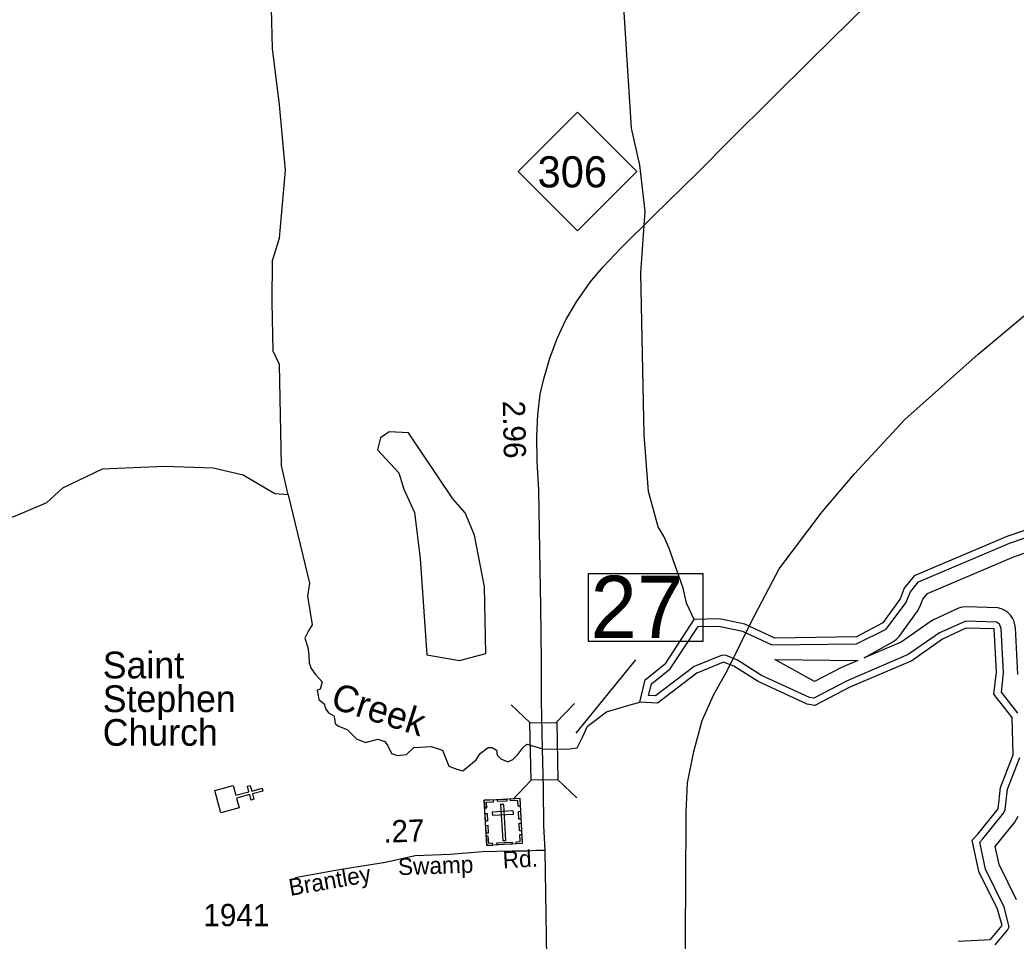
# Model space of a CAD drawing. Extents: x 2532689 to 2764727, y 536648 to 732970.
# Drawn here: x 2653505 to 2659104, y 576983 to 582158 of the extents above; entities that cross this region are included whole.
import ezdxf

# ---------------------------------------------------------------- set-up
doc = ezdxf.new("R2010")
doc.units = 0
for name, color, linetype in [('Exist Cultural Cemetery CELL', 7, 'Continuous'), ('Exist Cultural Church CELL', 7, 'Continuous'), ('Exist Cultural Church Label', 7, 'Continuous'), ('Exist Hydrographic Buffer Line', 7, 'Continuous'), ('Exist Hydrographic Creek Double Shore', 7, 'Continuous'), ('Exist Hydrographic Creek Single Shore', 7, 'Continuous'), ('Exist Hydrographic Creek Single Shore Label', 7, 'Continuous'), ('Exist Hydrographic Pond Under 1500 Sq Ft', 7, 'Continuous'), ('Exist Railroad Mainline', 7, 'Continuous'), ('Exist Road Primary NC Attributed', 7, 'Continuous'), ('Exist Road Primary NC Mileage Hundredths English Label', 7, 'Continuous'), ('Exist Road Primary NC Shield CELL', 7, 'Continuous'), ('Exist Road Primary NC Shield Number Label', 7, 'Continuous'), ('Exist Road Primary NC Structure Standard Bridge CELL', 7, 'Continuous'), ('Exist Road Primary NC Structure Standard Bridge Number Label', 7, 'Continuous'), ('Exist Road Secondary Mileage Hundredths English Label', 7, 'Continuous'), ('Exist Road Secondary Structure Standard Bridge Number Label', 7, 'Continuous'), ('Exist Road Secondary Type 20 Attributed', 7, 'Continuous'), ('Exist Road Secondary Type 51 Label', 7, 'Continuous'), ('Exist Road Secondary Type 51 Number Label', 7, 'Continuous')]:
    doc.layers.add(name, color=color, linetype=linetype)

msp = doc.modelspace()

# ---------------------------------------------------------------- linework, layer by layer
at = {"layer": 'Exist Cultural Cemetery CELL'}
for points in [[(2656115, 577774), (2656313.7, 577785.1), (2656327.9, 577530.9), (2656129.2, 577519.8)], [(2656117.4, 577730.8), (2656128.7, 577731.4), (2656126.9, 577763.5), (2656167.4, 577765.8), (2656166.8, 577776.9), (2656115, 577774)], [(2656188.9, 577778.1), (2656240.7, 577781), (2656241.3, 577769.6), (2656189.6, 577766.8)], [(2656316.2, 577741.8), (2656304.9, 577741.2), (2656303.1, 577773.3), (2656262.6, 577771.1), (2656262, 577782.2), (2656313.8, 577785.1)], [(2656159.5, 577708.3), (2656160.6, 577689.7), (2656278.1, 577696.3), (2656277.1, 577714.9)], [(2656225.5, 577750.8), (2656206.8, 577749.8), (2656218.1, 577547.3), (2656236.8, 577548.4)], [(2656308.9, 577668.2), (2656306.5, 577711.5), (2656317.9, 577712.1), (2656320.3, 577668.9)], [(2656121.5, 577656.7), (2656119.1, 577700), (2656130.5, 577700.6), (2656132.9, 577657.4)], [(2656125.2, 577589.6), (2656122.8, 577632.9), (2656134.2, 577633.5), (2656136.6, 577590.3)], [(2656312.6, 577602.4), (2656310.1, 577645.7), (2656321.5, 577646.3), (2656323.9, 577603)], [(2656162.2, 577521.7), (2656161.5, 577533.1), (2656139.6, 577531.9), (2656137.3, 577572.3), (2656126.2, 577571.7), (2656129.1, 577519.8)], [(2656294.9, 577529), (2656294.2, 577540.5), (2656316.2, 577541.7), (2656313.9, 577582.1), (2656325.1, 577582.7), (2656327.9, 577530.9)], [(2656185.9, 577534.5), (2656270.6, 577539.2), (2656271.3, 577527.8), (2656186.5, 577523.1)]]:
    msp.add_lwpolyline(points, close=True, dxfattribs=at)
at = {"layer": 'Exist Cultural Church CELL'}
msp.add_lwpolyline([(2654703.9, 577857.3), (2654718.7, 577802.4), (2654792.3, 577822), (2654784, 577853), (2654799.4, 577857.1), (2654807.7, 577826.2), (2654865.8, 577841.7), (2654870, 577826.2), (2654811.9, 577810.7), (2654820.1, 577779.8), (2654804.7, 577775.6), (2654796.4, 577806.6), (2654722.9, 577786.9), (2654737.7, 577731.2), (2654634.8, 577703.6), (2654601.1, 577829.8)], close=True, dxfattribs=at)
at = {"layer": 'Exist Hydrographic Buffer Line'}
for points in [[(2659113.8, 578263.7), (2659020.7, 578381.3), (2659033, 578490.3), (2659020.3, 578739.3), (2659011, 578762.8), (2658994, 578774.7), (2658822, 578780.6), (2658672.5, 578715.7), (2658497.4, 578592.7), (2658154.5, 578445.7), (2657966.3, 578347.7), (2657942.5, 578352.3), (2657672.5, 578475.8), (2657538.8, 578560.8), (2657474.4, 578587.9), (2657452.2, 578590.2), (2657295, 578526.1), (2657076.6, 578360.1), (2657038.4, 578362.2), (2657054.8, 578428.4), (2657159.4, 578513.3), (2657317.1, 578750.9), (2657433.2, 578752.9), (2657566.5, 578724.4), (2657730.3, 578647.9), (2658207, 578652.7), (2658372.9, 578735.6), (2658483.7, 578882.8), (2658509.9, 578945.6), (2658556, 579001.3), (2658987.7, 579184.6), (2659066.4, 579218.2), (2659478.4, 579359.2)], [(2659112.5, 578481.4), (2659100, 578743.6), (2659093.1, 578778.2), (2659084.2, 578797.1), (2659072.4, 578814.3), (2659057.6, 578829.1), (2659040.2, 578841.1), (2659021.3, 578849.9), (2659001, 578855.3), (2658823.8, 578860.5), (2658800.5, 578858.8), (2658780.2, 578853.3), (2658638.7, 578788.3), (2658619.8, 578777.4), (2658458.2, 578662.9), (2658249.9, 578573.6), (2658410.2, 578664.8), (2658431.6, 578679), (2658446.3, 578693.8), (2658548.7, 578836.2), (2658562.8, 578861.7), (2658579.8, 578904.4), (2658605.2, 578935.2), (2659019, 579111), (2659095.3, 579143.4), (2659504.2, 579283.5)], [(2657971.2, 578440.5), (2657747.3, 578564.1), (2658214.4, 578558.5), (2658123, 578519.2), (2657971.2, 578440.5)], [(2658986, 576962.3), (2659056, 577045.4), (2659064.8, 577064.1), (2659036.5, 577173.3), (2658931.3, 577387.5), (2658899.7, 577538), (2658917.5, 577556.9), (2659033.6, 577701.7), (2659042, 577722.1), (2659055.5, 577835.8), (2659124.4, 578014.5)], [(2659105.8, 577215.1), (2659007.6, 577413.9), (2658986.2, 577514.7), (2659095.9, 577651.8), (2659115, 577685.7)]]:
    msp.add_lwpolyline(points, dxfattribs=at)
at = {"layer": 'Exist Hydrographic Creek Double Shore'}
for points in [[(2660690.2, 579807.6), (2660566.4, 579763.2), (2660265.3, 579774.1), (2660140.3, 579769), (2659465.2, 579397), (2659052.3, 579255.5), (2658972.1, 579221.4)], [(2658972.1, 579221.4), (2658531.2, 579034.2), (2658475.2, 578966.2), (2658451.3, 578906.2), (2658354.3, 578770.9), (2658206.2, 578692.7), (2657747.1, 578684.1), (2657579.2, 578762.6), (2657437.3, 578793), (2657295.2, 578790.6)], [(2656988.2, 578325.1), (2657019.2, 578451.1), (2657134.2, 578544.4), (2657295.2, 578790.6)], [(2658980.3, 578737.2), (2658821.2, 578740.6), (2658689.3, 578679.4), (2658517.3, 578557.5), (2658170.1, 578408.9), (2657972.3, 578305.7), (2657930.2, 578313.9), (2657653.2, 578440.6), (2657517.2, 578527), (2657459.2, 578550.9), (2657310.1, 578489.1), (2657089.1, 578319.3), (2656988.2, 578325.1)], [(2658856.2, 577550.1), (2658888.2, 577584.2), (2659002.2, 577726.8), (2659016.4, 577845.5), (2659087.3, 578029), (2659082.2, 578238.9), (2658979.3, 578369.4), (2658993.2, 578494.7), (2658980.3, 578737.2)], [(2658777.3, 576982.2), (2658960.4, 576992.9), (2659025.2, 577071), (2658998.3, 577161.9), (2658893.3, 577374.3), (2658856.2, 577550.1)]]:
    msp.add_lwpolyline(points, dxfattribs=at)
at = {"layer": 'Exist Hydrographic Creek Single Shore'}
for points in [[(2655012.1, 579489.6), (2654975, 579655.6), (2654963.1, 580223.1), (2654928, 580297.2), (2654922.1, 580572.8), (2654925, 580806), (2654964.1, 580932.3), (2654996.9, 581314.6), (2654963.9, 581680.9), (2654923.9, 581997.8), (2654912.1, 582522.7), (2654874.9, 582672.2), (2654805, 582853.2), (2654659, 583034.5), (2654371.9, 583226.5), (2654048, 583512.2), (2653554, 583991.3), (2653322.9, 584287.3), (2652981.9, 584605.2), (2652783.8, 584892.7), (2652748.8, 584973.3), (2652593.9, 585229.7)], [(2657295.2, 578790.6), (2657251.1, 578880.7), (2657233.2, 578965.3), (2657153.1, 579188.7), (2657126.2, 579253.2), (2657092.2, 579310.9), (2657037.2, 579509.1), (2657014.2, 579826.5), (2656994.2, 580735.2), (2657019.2, 581084.3), (2656989, 581342.4), (2656942.1, 581550.7), (2656891, 582349.8), (2656863.1, 583639), (2656879.9, 584007.5), (2656883, 584608.4), (2656878.1, 584857.7)], [(2655012.1, 579489.6), (2654937.1, 579496.5), (2654760.1, 579600.9), (2654592, 579640.2), (2654317, 579648.7), (2653967, 579634.6), (2653745.1, 579527.1), (2653655.1, 579444.6), (2653465, 579364.7), (2653206, 579367.4), (2652500, 579634.4), (2652289, 579763.8), (2652000.9, 579991.8), (2651756.9, 580083.8), (2651371.8, 580143.7), (2650795.8, 580189.4), (2650603.9, 580201.3), (2650385.9, 580261.5)], [(2655012.1, 579489.6), (2655132.9, 578993.3), (2655121.8, 578920.8), (2655148, 578759.1), (2655126.8, 578725.7), (2655105.6, 578685.5), (2655123.4, 578633.1), (2655129, 578588.5), (2655130.1, 578547.2), (2655142.4, 578513.8), (2655166.9, 578480.3), (2655203.7, 578440.2), (2655193.1, 578398.9), (2655175.3, 578392.2), (2655182, 578362.1), (2655184.2, 578339.8), (2655214.3, 578316.4), (2655224.4, 578285.1), (2655240, 578266.2), (2655270.1, 578248.3), (2655273.4, 578232.7), (2655276.8, 578206), (2655294.6, 578190.3), (2655343.7, 578172.5), (2655396.1, 578120.1), (2655448, 578098.9), (2655516, 578116.7), (2655555, 578104.5), (2655572.9, 578079.9), (2655594.1, 578036.4), (2655626.4, 578025.3), (2655677.7, 578030.9), (2655717.9, 578071), (2655816, 578076.6), (2655879.6, 578056.5), (2655898.5, 578009.7), (2655916.4, 577966.2), (2655959.9, 577948.3), (2655993.3, 577939.4), (2656027.9, 577967.3), (2656068.6, 578000.7), (2656090.9, 578037.6), (2656136.6, 578071), (2656158.9, 578071), (2656183.5, 578055.4), (2656187.9, 578027.5), (2656208, 578006.3), (2656247, 577990.7), (2656274.9, 578003)], [(2656274.9, 578003), (2656302.8, 578032), (2656330.7, 578068.8), (2656354.1, 578088.9), (2656441.9, 578063.4), (2656581.6, 578062.1), (2656636.3, 578068.8), (2656667.5, 578129), (2656695.4, 578190.3), (2656801.3, 578270.6), (2656922.2, 578306), (2656988.2, 578325.1)]]:
    msp.add_lwpolyline(points, dxfattribs=at)
at = {"layer": 'Exist Hydrographic Pond Under 1500 Sq Ft'}
msp.add_lwpolyline([(2655580.1, 579844.2), (2655531.1, 579809.4), (2655515.1, 579743), (2655635.1, 579613.2), (2655662.1, 579522.5), (2655723, 579390.3), (2655754.2, 579132.1), (2655791.1, 578591.9), (2655975, 578559.9), (2656124.1, 578598.7), (2656116.1, 578972.8), (2656059.1, 579262.7), (2656007, 579388.7), (2655938.1, 579468), (2655688.2, 579838.7), (2655580.1, 579844.2)], dxfattribs=at)
at = {"layer": 'Exist Railroad Mainline'}
msp.add_lwpolyline([(2657243.3, 576807.6), (2657246.9, 577287.8), (2657249.3, 577707.8), (2657257.8, 577872.3), (2657292, 578049), (2657340.2, 578222), (2657404.9, 578367.5), (2657483.9, 578509.2), (2657617.7, 578782.2), (2657771.4, 579073.7), (2658014.6, 579395.2), (2658195.8, 579607.4), (2658478.9, 579913.6), (2658891, 580280.6), (2659537.4, 580819.3), (2660116.4, 581312.2), (2660831.2, 581921.9), (2661345.7, 582353.4)], dxfattribs=at)
at = {"layer": 'Exist Road Primary NC Attributed'}
for points in [[(2656428.5, 579067.3), (2656421.1, 579518.2), (2656412.7, 579677.7), (2656409.9, 579820.5), (2656415.5, 579940.9), (2656429.5, 580055.7), (2656449.1, 580142.5), (2656482.7, 580257.2), (2656524.7, 580367.5), (2656572.3, 580473.9), (2656633.9, 580574.7), (2656709.5, 580683.9), (2656782.3, 580770.7), (2656882.8, 580875.3), (2657066.3, 581056.8), (2657313.4, 581298.3), (2657502.5, 581489.2), (2657956.4, 581940.3), (2658592.5, 582566.6)], [(2656441.9, 578063.4), (2656436.5, 578332.6), (2656436.5, 578556.3), (2656433.4, 578866.2), (2656428.5, 579067.3)], [(2656457.2, 577491.2), (2656450, 577631.6), (2656447, 577841.2), (2656441.9, 578063.4)], [(2656510, 574218.4), (2656510, 574444.7), (2656500.8, 574719.7), (2656457.2, 577491.2)]]:
    msp.add_lwpolyline(points, dxfattribs=at)
at = {"layer": 'Exist Road Primary NC Shield CELL'}
msp.add_lwpolyline([(2656305.2, 581306.8), (2656638.2, 581639.8), (2656971.2, 581306.8), (2656638.2, 580973.8)], close=True, dxfattribs=at)
at = {"layer": 'Exist Road Primary NC Structure Standard Bridge CELL'}
for p, q in [((2656372.4, 578208.7), (2656266.2, 578310.5)), ((2656519.5, 578211.8), (2656621.3, 578318)), ((2656276.6, 577780.3), (2656378.5, 577886.5)), ((2656635.2, 577787.8), (2656529, 577889.7))]:
    msp.add_line(p, q, dxfattribs=at)
msp.add_lwpolyline([(2656378.5, 577886.5), (2656371.7, 578208.7), (2656522.2, 578211.8), (2656529, 577889.7)], close=True, dxfattribs=at)
at = {"layer": 'Exist Road Primary NC Structure Standard Bridge Number Label'}
msp.add_lwpolyline([(2656699.8, 579047.8), (2657343.9, 579047.8), (2657343.9, 578665.5), (2656699.8, 578665.5)], close=True, dxfattribs=at)
at = {"layer": 'Exist Road Secondary Structure Standard Bridge Number Label'}
msp.add_line((2656631.6, 578151.7), (2656966.6, 578564), dxfattribs=at)
at = {"layer": 'Exist Road Secondary Type 20 Attributed'}
msp.add_lwpolyline([(2656457.2, 577491.2), (2656408, 577491.2), (2656354.5, 577489), (2656271.4, 577487.9), (2656104.2, 577484.6), (2655922.6, 577468.7), (2655726.5, 577462.1), (2655559.3, 577424.5), (2655298.3, 577382.7), (2655051.2, 577339.3)], dxfattribs=at)

# ---------------------------------------------------------------- texts
at = {"layer": 'Exist Cultural Church Label'}
for s, p in [('Saint', (2653970.5, 578459.1)), ('Stephen', (2653970.5, 578269.7)), ('Church', (2653970.5, 578080.3))]:
    msp.add_text(s, height=150, dxfattribs=at).set_placement(p)
at = {"layer": 'Exist Hydrographic Creek Single Shore Label'}
msp.add_text('Creek', height=150, rotation=342.2694, dxfattribs=at).set_placement((2655244.5, 578295.2))
at = {"layer": 'Exist Road Primary NC Mileage Hundredths English Label'}
msp.add_text('2.96', height=125, rotation=271.1239, dxfattribs=at).set_placement((2656218.6, 580018.2))
at = {"layer": 'Exist Road Primary NC Shield Number Label'}
msp.add_text('306', height=175, dxfattribs=at).set_placement((2656414.3, 581217.1))
at = {"layer": 'Exist Road Primary NC Structure Standard Bridge Number Label'}
msp.add_text('27', height=350, dxfattribs=at).set_placement((2656712.3, 578685.3))
at = {"layer": 'Exist Road Secondary Mileage Hundredths English Label'}
msp.add_text('.27', height=125, rotation=1.93, dxfattribs=at).set_placement((2655548.9, 577535.4))
at = {"layer": 'Exist Road Secondary Type 51 Label'}
for s, rotation, p in [('Rd.', 3.1972, (2656220.8, 577391.1)), ('Swamp', 1.93, (2655631.4, 577353.3)), ('Brantley', 9.9764, (2655025, 577236.5))]:
    msp.add_text(s, height=95, rotation=rotation, dxfattribs=at).set_placement(p)
at = {"layer": 'Exist Road Secondary Type 51 Number Label'}
msp.add_text('1941', height=125, dxfattribs=at).set_placement((2654535.7, 577066.9))

doc.saveas('drawing.dxf')
